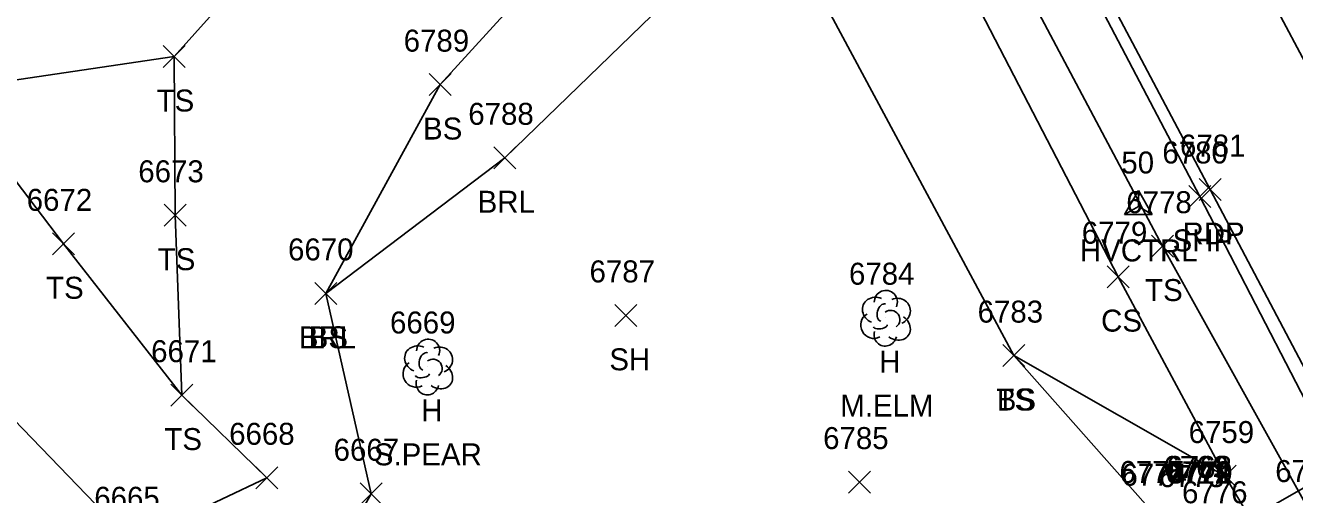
# Model space of a CAD drawing. Extents: x 1439173 to 1457902, y 641926 to 659889.
# Drawn here: x 1448707.4 to 1448822.7, y 643807.3 to 643850 of the extents above; entities that cross this region are included whole.
import ezdxf

# ---------------------------------------------------------------- set-up
doc = ezdxf.new("R2010")
doc.units = 0
for name, color, linetype in [('C_A', 7, 'Continuous'), ('C_I', 7, 'Continuous'), ('CPSM', 7, 'Continuous'), ('D_I', 7, 'Continuous'), ('DDEFAULT', 7, 'Continuous'), ('L_A', 7, 'Continuous'), ('L_C', 7, 'Continuous'), ('L_I', 7, 'Continuous'), ('L_TIC', 7, 'Continuous'), ('LABL', 7, 'Continuous'), ('LELB', 7, 'Continuous'), ('LTD', 7, 'Continuous'), ('P_A', 7, 'Continuous'), ('P_I', 7, 'Continuous'), ('P_TIC', 7, 'Continuous'), ('PET', 7, 'Continuous'), ('PRC', 7, 'Continuous'), ('PSP', 7, 'Continuous')]:
    doc.layers.add(name, color=color, linetype=linetype)

msp = doc.modelspace()

# ---------------------------------------------------------------- linework, layer by layer
at = {"layer": 'CPSM'}
for p, q in [((1448807.28, 643832.79), (1448808.53, 643834.96)), ((1448809.78, 643832.79), (1448808.53, 643834.96)), ((1448808.53, 643833.52), (1448808.53, 643834.96)), ((1448807.28, 643832.79), (1448808.53, 643833.52)), ((1448808.53, 643833.52), (1448808.53, 643833.52)), ((1448808.53, 643833.52), (1448809.78, 643832.79)), ((1448807.28, 643832.79), (1448809.78, 643832.79))]:
    msp.add_line(p, q, dxfattribs=at)
at = {"layer": 'DDEFAULT'}
msp.add_lwpolyline([(1448815.86, 643803.51), (1448863.66, 643830.86)], dxfattribs=at)
at = {"layer": 'L_TIC'}
for points in [[(1448719.9, 643846.16), (1448721.9, 643848.16)], [(1448721.9, 643846.16), (1448719.9, 643848.16)], [(1448719.9, 643846.16), (1448721.9, 643848.16)], [(1448721.9, 643846.16), (1448719.9, 643848.16)], [(1448744.08, 643843.61), (1448746.08, 643845.61)], [(1448746.08, 643843.61), (1448744.08, 643845.61)], [(1448749.94, 643836.95), (1448751.94, 643838.95)], [(1448751.94, 643836.95), (1448749.94, 643838.95)], [(1448720, 643831.72), (1448722, 643833.72)], [(1448722, 643831.72), (1448720, 643833.72)], [(1448709.85, 643829.12), (1448711.85, 643831.12)], [(1448711.85, 643829.12), (1448709.85, 643831.12)], [(1448809.73, 643828.91), (1448811.73, 643830.91)], [(1448811.73, 643828.91), (1448809.73, 643830.91)], [(1448805.7, 643826.13), (1448807.7, 643828.13)], [(1448807.7, 643826.13), (1448805.7, 643828.13)], [(1448733.69, 643824.61), (1448735.69, 643826.61)], [(1448735.69, 643824.61), (1448733.69, 643826.61)], [(1448733.69, 643824.61), (1448735.69, 643826.61)], [(1448735.69, 643824.61), (1448733.69, 643826.61)], [(1448760.96, 643822.61), (1448762.96, 643824.61)], [(1448762.96, 643822.61), (1448760.96, 643824.61)], [(1448796.22, 643818.95), (1448798.22, 643820.95)], [(1448798.22, 643818.95), (1448796.22, 643820.95)], [(1448796.22, 643818.95), (1448798.22, 643820.95)], [(1448798.22, 643818.95), (1448796.22, 643820.95)], [(1448720.6, 643815.35), (1448722.6, 643817.35)], [(1448722.6, 643815.35), (1448720.6, 643817.35)], [(1448720.6, 643815.35), (1448722.6, 643817.35)], [(1448722.6, 643815.35), (1448720.6, 643817.35)], [(1448728.31, 643807.83), (1448730.31, 643809.83)], [(1448730.31, 643807.83), (1448728.31, 643809.83)], [(1448728.31, 643807.83), (1448730.31, 643809.83)], [(1448730.31, 643807.83), (1448728.31, 643809.83)], [(1448815.41, 643807.99), (1448817.41, 643809.99)], [(1448817.41, 643807.99), (1448815.41, 643809.99)], [(1448815.41, 643807.99), (1448817.41, 643809.99)], [(1448817.41, 643807.99), (1448815.41, 643809.99)], [(1448782.19, 643807.44), (1448784.19, 643809.44)], [(1448784.19, 643807.44), (1448782.19, 643809.44)], [(1448737.8, 643806.38), (1448739.8, 643808.38)], [(1448739.8, 643806.38), (1448737.8, 643808.38)]]:
    msp.add_lwpolyline(points, dxfattribs=at)
at = {"layer": 'LABL'}
msp.add_lwpolyline([(1448726.59, 643633.06), (1448720.88, 643665.88), (1448721.81, 643679.51), (1448713.75, 643699.28), (1448716.48, 643738.3), (1448713.98, 643745.94), (1448716.58, 643759.48), (1448721.16, 643766.42), (1448727.6, 643780.65), (1448730.59, 643792.75), (1448738.8, 643807.38), (1448734.69, 643825.61), (1448750.94, 643837.95), (1448770.04, 643856.47), (1448769.85, 643865.62), (1448759.86, 643877.1), (1448756.96, 643880.01), (1448752.9, 643888.77), (1448756.9, 643896.92), (1448747.89, 643914.13), (1448730.84, 643886.4), (1448712.52, 643872.63), (1448692.92, 643859.64), (1448664.81, 643844.84)], dxfattribs=at)
at = {"layer": 'LELB'}
for points in [[(1448940.79, 643577.93), (1448919.27, 643624.16), (1448900.78, 643658.74), (1448885.8, 643689.16), (1448877.75, 643703.58), (1448856.47, 643745.03), (1448837.55, 643780.25), (1448824.28, 643805.44), (1448810.73, 643829.91), (1448787.2, 643874.29), (1448782.43, 643882.71), (1448771.37, 643901.56), (1448759.4, 643927.61), (1448747.42, 643949.44), (1448734.25, 643972.55), (1448714.17, 644015.51), (1448690.32, 644058.37)], [(1448931.66, 643587.96), (1448924.07, 643603.5), (1448916.12, 643618.4), (1448906.54, 643637.63), (1448900.76, 643649.84), (1448881.42, 643686.55), (1448871.3, 643700.15), (1448853.2, 643742.83), (1448833.78, 643778.7), (1448820.49, 643802.12), (1448816.41, 643808.99), (1448806.7, 643827.13), (1448783.89, 643871.22), (1448779.41, 643878.86), (1448774.04, 643881.68)], [(1448729.31, 643808.83), (1448721.6, 643816.35), (1448721, 643832.72), (1448720.9, 643847.16), (1448731.63, 643859.14), (1448756.96, 643880.01)], [(1448810.12, 643805.36), (1448797.22, 643819.95), (1448776.65, 643858.32), (1448776.39, 643873.03), (1448774.02, 643875.39), (1448771.82, 643874.03), (1448769.85, 643865.62)], [(1448734.69, 643825.61), (1448745.08, 643844.61), (1448757.29, 643858.03), (1448770.04, 643856.47)], [(1448720.9, 643847.16), (1448700.21, 643844.09)], [(1448721.6, 643816.35), (1448710.85, 643830.12), (1448700.21, 643844.09), (1448679.68, 643835.36), (1448663.97, 643817.83), (1448664.73, 643788.01), (1448683.17, 643756.83), (1448696.64, 643739.78)], [(1448713.98, 643745.94), (1448696.76, 643759.42), (1448690.78, 643771.36), (1448682.01, 643789.5), (1448677.88, 643809.11), (1448688.03, 643822.09), (1448704.66, 643815.84), (1448717.04, 643803.01), (1448729.31, 643808.83)], [(1448816.41, 643808.99), (1448797.22, 643819.95)]]:
    msp.add_lwpolyline(points, dxfattribs=at)
at = {"layer": 'LTD'}
for p, q in [((1448785.53, 643823.4), (1448785.53, 643823.4)), ((1448785.53, 643823.4), (1448785.53, 643823.4)), ((1448743.93, 643818.96), (1448743.93, 643818.96)), ((1448743.93, 643818.96), (1448743.93, 643818.96))]:
    msp.add_line(p, q, dxfattribs=at)
for centre in [(1448785.58, 643824.83), (1448743.98, 643820.39)]:
    msp.add_arc(centre, 1.05, 335.5272, 180.9563, dxfattribs=at)
for centre, major_axis, ratio, start_param, end_param in [((1448784.74, 643824.06), (1.21, -0.51), 0.895232, 1.570796, 4.712389), ((1448786.58, 643823.98), (-1.14, -0.48), 0.949671, 1.570796, 4.712389), ((1448784.45, 643822.69), (0.58, -1.04), 0.959034, 3.141593, 6.283185), ((1448785.33, 643823.86), (-0.208, -0.792), 0.645439, 3.141593, 6.283185), ((1448786.03, 643823.23), (-0.5, 0.667), 0.989748, 3.141593, 6.283185), ((1448785.08, 643822.65), (-0.625, -0.083), 0.423636, 0, 3.141593), ((1448786.53, 643822.56), (-1.09, 0.79), 0.841452, 1.570796, 4.712389), ((1448785.54, 643821.9), (0.26, 1.06), 0.942809, 1.570796, 4.712389), ((1448743.14, 643819.63), (1.21, -0.51), 0.895232, 1.570796, 4.712389), ((1448743.72, 643819.42), (-0.208, -0.792), 0.645439, 3.141593, 6.283185), ((1448744.97, 643819.54), (-1.14, -0.48), 0.949671, 1.570796, 4.712389), ((1448742.85, 643818.25), (0.58, -1.04), 0.959034, 3.141593, 6.283185), ((1448744.43, 643818.79), (-0.5, 0.667), 0.989748, 3.141593, 6.283185), ((1448744.93, 643818.13), (-1.09, 0.79), 0.841452, 1.570796, 4.712389), ((1448743.47, 643818.21), (-0.625, -0.083), 0.423636, 0, 3.141593), ((1448743.93, 643817.46), (0.26, 1.06), 0.942809, 1.570796, 4.712389)]:
    msp.add_ellipse(centre, major_axis=major_axis, ratio=ratio, start_param=start_param, end_param=end_param, dxfattribs=at)
at = {"layer": 'P_TIC'}
for points in [[(1448813.1, 643833.43), (1448815.1, 643835.43)], [(1448815.1, 643833.43), (1448813.1, 643835.43)], [(1448814.05, 643834.06), (1448816.05, 643836.06)], [(1448816.05, 643834.06), (1448814.05, 643836.06)]]:
    msp.add_lwpolyline(points, dxfattribs=at)
at = {"layer": 'PET'}
msp.add_lwpolyline([(1449139.97, 643188.13), (1449117.6, 643232.77), (1449099.11, 643273.2), (1449066.34, 643340.97), (1449039.44, 643395.72), (1449020.72, 643432.95), (1449000.27, 643474.21), (1448984.45, 643505.7), (1448966.63, 643542.12), (1448946.78, 643580.8), (1448923.53, 643626.67), (1448906.33, 643660.76), (1448890.57, 643691.55), (1448882.77, 643706.14), (1448861.66, 643747.38), (1448842.89, 643782.5), (1448829.18, 643808.28), (1448815.05, 643835.06), (1448764.92, 643929.88), (1448739.21, 643978.47), (1448719.14, 644017.8), (1448697.57, 644061.64)], dxfattribs=at)
at = {"layer": 'PRC'}
msp.add_lwpolyline([(1449151.13, 643193.26), (1449129.92, 643237.18), (1449110.21, 643278.66), (1449077.82, 643346.33), (1449052.31, 643400.08), (1449033.57, 643437.64), (1449013.31, 643480.22), (1448998.17, 643509.98), (1448979.42, 643547.94), (1448960, 643587.03), (1448936.54, 643632.54), (1448918.64, 643666.68), (1448902.12, 643697.96), (1448893.71, 643713.68), (1448873.04, 643753.33), (1448854.51, 643788.55), (1448840.55, 643814.74), (1448825.9, 643842.48), (1448798.39, 643894.2), (1448777.05, 643935.06), (1448750.78, 643985.2), (1448731.14, 644023.28), (1448710.46, 644067.89)], dxfattribs=at)
at = {"layer": 'PSP'}
msp.add_lwpolyline([(1448943.46, 643579.59), (1448921.84, 643625.91), (1448904.32, 643659.57), (1448888.54, 643690.76), (1448881.08, 643705.57), (1448860.26, 643746.81), (1448841.85, 643781.75), (1448827.91, 643807.72), (1448814.1, 643834.43), (1448788.68, 643883.02), (1448774.83, 643907.87), (1448763.64, 643929.45), (1448738.41, 643977.89), (1448718.77, 644017.47), (1448697.57, 644061.64)], dxfattribs=at)

# ---------------------------------------------------------------- texts
at = {"layer": 'C_A'}
msp.add_text('HVCTRL', height=2, dxfattribs=at).set_placement((1448803.22, 643828.52))
at = {"layer": 'C_I'}
msp.add_text('50', height=2, dxfattribs=at).set_placement((1448806.98, 643836.52))
at = {"layer": 'D_I'}
for s, p in [('6775', (1448806.81, 643808.36)), ('6769', (1448810.81, 643808.81)), ('6768', (1448811.08, 643808.81)), ('6770', (1448811.13, 643808.33)), ('6771', (1448811.2, 643808.31)), ('6776', (1448812.5, 643806.51))]:
    msp.add_text(s, height=2, dxfattribs=at).set_placement(p)
at = {"layer": 'L_A'}
for s, p in [('TS', (1448719.31, 643842.16)), ('TS', (1448719.31, 643842.16)), ('BS', (1448743.52, 643839.61)), ('BRL', (1448748.48, 643832.95)), ('TS', (1448719.41, 643827.72)), ('TS', (1448709.26, 643825.12)), ('TS', (1448809.14, 643824.91)), ('CS', (1448805.14, 643822.13)), ('BRL', (1448732.23, 643820.61)), ('BS', (1448733.13, 643820.61)), ('SH', (1448760.45, 643818.61)), ('H', (1448784.97, 643818.4)), ('TS', (1448795.63, 643814.95)), ('BS', (1448795.66, 643814.95)), ('H', (1448743.36, 643813.96)), ('TS', (1448720.01, 643811.35)), ('TS', (1448720.01, 643811.35))]:
    msp.add_text(s, height=2, dxfattribs=at).set_placement(p)
at = {"layer": 'L_C'}
for s, p in [('M.ELM', (1448781.44, 643814.4)), ('S.PEAR', (1448739.05, 643809.96))]:
    msp.add_text(s, height=2, dxfattribs=at).set_placement(p)
at = {"layer": 'L_I'}
for s, p in [('6789', (1448741.76, 643847.61)), ('6788', (1448747.63, 643840.95)), ('6673', (1448717.64, 643835.72)), ('6672', (1448707.5, 643833.12)), ('6778', (1448807.43, 643832.91)), ('6779', (1448803.39, 643830.13)), ('6670', (1448731.25, 643828.61)), ('6670', (1448731.25, 643828.61)), ('6787', (1448758.65, 643826.61)), ('6784', (1448782.23, 643826.4)), ('6783', (1448793.92, 643822.95)), ('6783', (1448793.92, 643822.95)), ('6669', (1448740.52, 643821.96)), ('6671', (1448718.81, 643819.35)), ('6671', (1448718.81, 643819.35)), ('6668', (1448725.9, 643811.83)), ('6668', (1448725.9, 643811.83)), ('6785', (1448779.88, 643811.44)), ('6759', (1448813.1, 643811.99)), ('6759', (1448813.1, 643811.99)), ('6667', (1448735.39, 643810.38)), ('6775', (1448806.81, 643808.36)), ('6775', (1448806.81, 643808.36)), ('6774', (1448806.99, 643808.11)), ('6774', (1448806.99, 643808.11)), ('6773', (1448810.4, 643807.98)), ('6772', (1448811, 643808.32)), ('6755', (1448820.97, 643808.44)), ('6665', (1448713.64, 643806.01))]:
    msp.add_text(s, height=2, dxfattribs=at).set_placement(p)
at = {"layer": 'P_A'}
for s, p in [('RDP', (1448812.54, 643830.06)), ('SHP', (1448811.64, 643829.43))]:
    msp.add_text(s, height=2, dxfattribs=at).set_placement(p)
at = {"layer": 'P_I'}
for s, p in [('6781', (1448812.31, 643838.06)), ('6780', (1448810.71, 643837.43))]:
    msp.add_text(s, height=2, dxfattribs=at).set_placement(p)

doc.saveas('drawing.dxf')
